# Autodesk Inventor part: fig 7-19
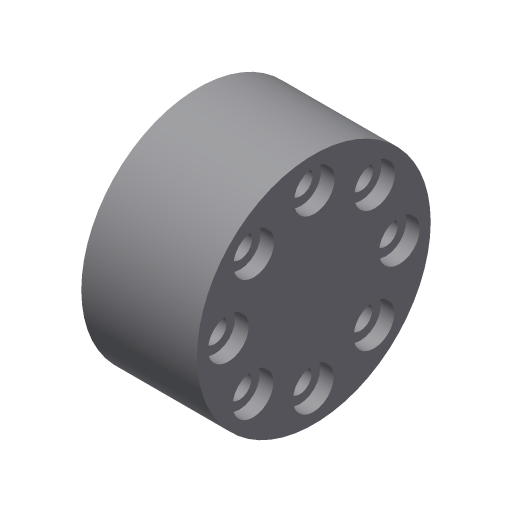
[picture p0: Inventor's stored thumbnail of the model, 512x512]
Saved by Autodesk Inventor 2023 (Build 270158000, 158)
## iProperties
Created: 2004-05
Part Number: fig 7-19
Document SubType Name: Modeling
Designer: CADCIM Technologies
Manufacturer: Standard
Standards Organization: Custom
Density: 1 g/cm^3
Material: Generic
Appearance: Default
Author: CADCIM Technologies
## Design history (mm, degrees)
sketch "Sketch1"
  geometry: C1 r 17.175 at (0, 0)
  constraints: 1 centre point
extrude "Extrusion1" new body sketch "Sketch1" distance "d0" = 17; taper "d1" = 0 deg
sketch "Sketch2"
  geometry: 1 further point
hole "Hole1" sketch "Sketch2" at (12.571, -0.074) diameter "d2" = 3.5; stored, may be unused: countersink angle "d6" = 90 deg, drill point angle "d8" = 118 deg; dims "d3" = 6, "d4" = 6, "d5" = 2, "d7" = 8
pattern_circular "Circular Pattern1" dims angle "d11" = 360 deg
body "Solid1"
